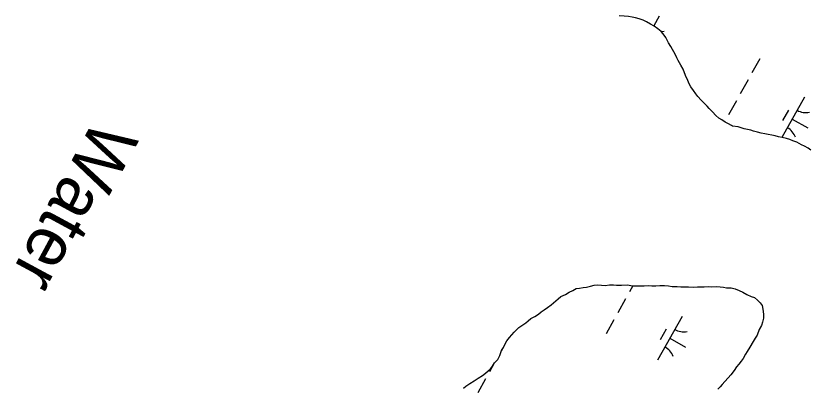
# Model space of a CAD drawing. Extents: x 3923531 to 3943530, y 207391 to 229799.
# Drawn here: x 3927358 to 3928152, y 213557 to 213929 of the extents above; entities that cross this region are included whole.
import ezdxf

# ---------------------------------------------------------------- set-up
doc = ezdxf.new("R2010")
doc.units = 0
doc.layers.add('V-RIVR-IDEN', color=7, linetype='Continuous')
doc.layers.add('V-WETL-SWMP', color=7, linetype='Continuous')

msp = doc.modelspace()

# ---------------------------------------------------------------- linework, layer by layer
at = {"layer": 'V-WETL-SWMP'}
for p, q in [((3927966.19, 213928.5), (3927961.2, 213928.91)), ((3927970.49, 213928.44), (3927966.19, 213928.5)), ((3927974.27, 213927.53), (3927970.49, 213928.44)), ((3927977.71, 213926.97), (3927974.27, 213927.53)), ((3927981.31, 213926.06), (3927977.71, 213926.97)), ((3927985.25, 213924.63), (3927981.31, 213926.06)), ((3928001.33, 213928.76), (3927995.87, 213918.99)), ((3927988.68, 213923.03), (3927985.25, 213924.63)), ((3927992.78, 213920.74), (3927988.68, 213923.03)), ((3927996.2, 213918.8), (3927992.78, 213920.74)), ((3927999.95, 213916), (3927996.2, 213918.8)), ((3928003.19, 213913.2), (3927999.95, 213916)), ((3928005.4, 213910.93), (3928003.19, 213913.2)), ((3928007.93, 213907.28), (3928005.4, 213910.93)), ((3928010.79, 213902.07), (3928007.93, 213907.28)), ((3928012.98, 213898.26), (3928010.79, 213902.07)), ((3928014.66, 213895.31), (3928012.98, 213898.26)), ((3928017.19, 213890.8), (3928014.66, 213895.31)), ((3928019.03, 213887.15), (3928017.19, 213890.8)), ((3928020.37, 213884.21), (3928019.03, 213887.15)), ((3928101.87, 213886), (3928094.06, 213872.04)), ((3928022.89, 213879.52), (3928020.37, 213884.21)), ((3928025.25, 213875.53), (3928022.89, 213879.52)), ((3928027.58, 213869.3), (3928025.25, 213875.53)), ((3928029.93, 213864.45), (3928027.58, 213869.3)), ((3928031.43, 213860.98), (3928029.93, 213864.45)), ((3928090.16, 213865.05), (3928082.36, 213851.08)), ((3928033.11, 213857.86), (3928031.43, 213860.98)), ((3928035.65, 213854.21), (3928033.11, 213857.86)), ((3928038.01, 213850.91), (3928035.65, 213854.21)), ((3928040.05, 213848.3), (3928038.01, 213850.91)), ((3928043.27, 213844.64), (3928040.05, 213848.3)), ((3928146.54, 213847.64), (3928124.02, 213807.32)), ((3928046.16, 213841.67), (3928043.27, 213844.64)), ((3928049.22, 213838.53), (3928046.16, 213841.67)), ((3928051.43, 213836.26), (3928049.22, 213838.53)), ((3928078.46, 213844.1), (3928070.65, 213830.13)), ((3928054.65, 213832.95), (3928051.43, 213836.26)), ((3928057.88, 213829.46), (3928054.65, 213832.95)), ((3928061.12, 213826.66), (3928057.88, 213829.46)), ((3928130.54, 213834.81), (3928124.69, 213824.34)), ((3928063.85, 213824.9), (3928061.12, 213826.66)), ((3928067.44, 213822.79), (3928063.85, 213824.9)), ((3928070.69, 213821.02), (3928067.44, 213822.79)), ((3928134.35, 213825.81), (3928150.07, 213817.03)), ((3928073.77, 213819.43), (3928070.69, 213821.02)), ((3928074.79, 213818.56), (3928073.77, 213819.43)), ((3928080.29, 213818.14), (3928074.79, 213818.56)), ((3928083.2, 213816.9), (3928080.29, 213818.14)), ((3928086.29, 213816), (3928083.2, 213816.9)), ((3928089.55, 213815.26), (3928086.29, 213816)), ((3928092.82, 213814.53), (3928089.55, 213815.26)), ((3928095.73, 213813.63), (3928092.82, 213814.53)), ((3928099.68, 213812.72), (3928095.73, 213813.63)), ((3928103.29, 213811.81), (3928099.68, 213812.72)), ((3928107.07, 213811.07), (3928103.29, 213811.81)), ((3928110.33, 213810.34), (3928107.07, 213811.07)), ((3928114.11, 213809.6), (3928110.33, 213810.34)), ((3928117.37, 213809.04), (3928114.11, 213809.6)), ((3928120.63, 213808.14), (3928117.37, 213809.04)), ((3928124.41, 213807.22), (3928120.63, 213808.14)), ((3928128.53, 213806.48), (3928124.41, 213807.22)), ((3928131.79, 213805.4), (3928128.53, 213806.48)), ((3928135.05, 213804.16), (3928131.79, 213805.4)), ((3928138.82, 213802.56), (3928135.05, 213804.16)), ((3928143.61, 213800.08), (3928138.82, 213802.56)), ((3928146.51, 213798.66), (3928143.61, 213800.08)), ((3928150.28, 213796.55), (3928146.51, 213798.66)), ((3928152.84, 213794.79), (3928150.28, 213796.55)), ((3927915.02, 213654.39), (3927918.18, 213656.32)), ((3927918.18, 213656.32), (3927921.72, 213656.66)), ((3927921.72, 213656.66), (3927925.27, 213657.4)), ((3927925.27, 213657.4), (3927928.81, 213657.74)), ((3927928.81, 213657.74), (3927932.75, 213658.87)), ((3927932.75, 213658.87), (3927936.29, 213659.61)), ((3927936.29, 213659.61), (3927939.44, 213659.96)), ((3927939.44, 213659.96), (3927943.76, 213659.9)), ((3927943.76, 213659.9), (3927947.29, 213659.46)), ((3927947.29, 213659.46), (3927951.62, 213660.19)), ((3927951.62, 213660.19), (3927955.54, 213660.14)), ((3927955.54, 213660.14), (3927958.68, 213659.71)), ((3927958.68, 213659.71), (3927963.79, 213659.64)), ((3927963.79, 213659.64), (3927969.68, 213659.95)), ((3927969.68, 213659.95), (3927974.77, 213659.1)), ((3927975.1, 213659.1), (3927971.67, 213652.95)), ((3927974.77, 213659.1), (3927979.09, 213659.04)), ((3927979.09, 213659.04), (3927983.02, 213658.99)), ((3927983.02, 213658.99), (3927986.16, 213658.95)), ((3927986.16, 213658.95), (3927990.88, 213659.28)), ((3927990.88, 213659.28), (3927994.02, 213659.24)), ((3927994.02, 213659.24), (3927997.95, 213659.19)), ((3927997.95, 213659.19), (3928001.88, 213659.53)), ((3928001.88, 213659.53), (3928006.59, 213659.46)), ((3928006.59, 213659.46), (3928010.51, 213659.02)), ((3928010.51, 213659.02), (3928014.43, 213658.58)), ((3928014.43, 213658.58), (3928019.15, 213658.51)), ((3928019.15, 213658.51), (3928023.07, 213658.07)), ((3928023.07, 213658.07), (3928026.6, 213658.02)), ((3928026.6, 213658.02), (3928030.53, 213657.97)), ((3928030.53, 213657.97), (3928035.24, 213657.91)), ((3928035.24, 213657.91), (3928039.56, 213658.24)), ((3928039.56, 213658.24), (3928042.71, 213658.2)), ((3928042.71, 213658.2), (3928046.24, 213658.15)), ((3928046.24, 213658.15), (3928050.56, 213658.49)), ((3928050.56, 213658.49), (3928053.7, 213658.06)), ((3928053.7, 213658.06), (3928058.81, 213658.38)), ((3928058.81, 213658.38), (3928062.34, 213657.94)), ((3928062.34, 213657.94), (3928065.48, 213657.9)), ((3928065.48, 213657.9), (3928068.61, 213657.07)), ((3928068.61, 213657.07), (3928073.32, 213657.01)), ((3928073.32, 213657.01), (3928077.24, 213656.17)), ((3928077.24, 213656.17), (3928081.15, 213654.55)), ((3927900.37, 213645.95), (3927903.15, 213648.27)), ((3927903.15, 213648.27), (3927907.5, 213650.57)), ((3927907.5, 213650.57), (3927911.46, 213652.87)), ((3927911.46, 213652.87), (3927915.02, 213654.39)), ((3928081.15, 213654.55), (3928085.05, 213652.93)), ((3928085.05, 213652.93), (3928088.95, 213650.52)), ((3928088.95, 213650.52), (3928093.24, 213648.5)), ((3928093.24, 213648.5), (3928096.76, 213647.28)), ((3928096.76, 213647.28), (3928099.48, 213644.88)), ((3927889.66, 213637.45), (3927893.23, 213640.15)), ((3927893.23, 213640.15), (3927897.99, 213644.01)), ((3927897.99, 213644.01), (3927900.37, 213645.95)), ((3927967.77, 213645.97), (3927959.97, 213632)), ((3928099.48, 213644.88), (3928102.19, 213642.1)), ((3928102.19, 213642.1), (3928104.12, 213639.32)), ((3928104.12, 213639.32), (3928104.85, 213635.78)), ((3927880.54, 213630.89), (3927883.32, 213633.21)), ((3927883.32, 213633.21), (3927886.48, 213635.13)), ((3927886.48, 213635.13), (3927889.66, 213637.45)), ((3928104.85, 213635.78), (3928105.57, 213630.66)), ((3927867.85, 213622.03), (3927870.23, 213623.96)), ((3927870.23, 213623.96), (3927873.01, 213626.28)), ((3927873.01, 213626.28), (3927876.97, 213628.58)), ((3927876.97, 213628.58), (3927880.54, 213630.89)), ((3927956.06, 213625.02), (3927948.26, 213611.05)), ((3928024.15, 213628.55), (3927999.77, 213584.9)), ((3928105.52, 213626.74), (3928104.68, 213622.82)), ((3928105.57, 213630.66), (3928105.52, 213626.74)), ((3927856.34, 213612.75), (3927858.73, 213615.08)), ((3927858.73, 213615.08), (3927861.12, 213617.4)), ((3927861.12, 213617.4), (3927863.89, 213619.33)), ((3927863.89, 213619.33), (3927867.85, 213622.03)), ((3928008.15, 213615.73), (3928002.3, 213605.25)), ((3928101.44, 213615.4), (3928099.41, 213609.93)), ((3928103.46, 213619.3), (3928101.44, 213615.4)), ((3928104.68, 213622.82), (3928103.46, 213619.3)), ((3927849.16, 213604.21), (3927851.56, 213607.32)), ((3927851.56, 213607.32), (3927853.95, 213610.04)), ((3927853.95, 213610.04), (3927856.34, 213612.75)), ((3928099.41, 213609.93), (3928097.4, 213606.82)), ((3927845.54, 213597.58), (3927847.14, 213600.31)), ((3927847.14, 213600.31), (3927849.16, 213604.21)), ((3928011.96, 213606.73), (3928027.67, 213597.95)), ((3928095.39, 213603.31), (3928091.79, 213597.86)), ((3928097.4, 213606.82), (3928095.39, 213603.31)), ((3927841.89, 213589.38), (3927843.53, 213594.46)), ((3927844.32, 213595.7), (3927843.39, 213594.03)), ((3927843.53, 213594.46), (3927845.54, 213597.58)), ((3928089.37, 213593.57), (3928087.77, 213590.84)), ((3928091.79, 213597.86), (3928089.37, 213593.57)), ((3927836.69, 213581.99), (3927839.88, 213585.48)), ((3927839.88, 213585.48), (3927841.89, 213589.38)), ((3928083.35, 213583.83), (3928080.96, 213580.72)), ((3928085.35, 213586.55), (3928083.35, 213583.83)), ((3928087.77, 213590.84), (3928085.35, 213586.55)), ((3927830.3, 213574.22), (3927832.68, 213576.15)), ((3927836.51, 213581.71), (3927831.69, 213573.08)), ((3927832.68, 213576.15), (3927834.68, 213578.87)), ((3927834.68, 213578.87), (3927836.69, 213581.99)), ((3928078.56, 213578), (3928076.16, 213574.5)), ((3928080.96, 213580.72), (3928078.56, 213578)), ((3927820.39, 213566.89), (3927824.74, 213569.58)), ((3927824.74, 213569.58), (3927827.52, 213571.9)), ((3927827.52, 213571.9), (3927830.3, 213574.22)), ((3928072.96, 213570.22), (3928070.17, 213567.12)), ((3928076.16, 213574.5), (3928072.96, 213570.22)), ((3927808.1, 213558.8), (3927812.07, 213561.5)), ((3927812.07, 213561.5), (3927816.42, 213564.19)), ((3927816.42, 213564.19), (3927820.39, 213566.89)), ((3927827.79, 213566.09), (3927819.98, 213552.13)), ((3928064.19, 213560.52), (3928062.2, 213558.19)), ((3928066.98, 213563.62), (3928064.19, 213560.52)), ((3928070.17, 213567.12), (3928066.98, 213563.62)), ((3927805.72, 213556.87), (3927808.1, 213558.8)), ((3928062.2, 213558.19), (3928059.81, 213555.86))]:
    msp.add_line(p, q, dxfattribs=at)
for centre, start, end in [((3928002.82, 213930.93), 270.77039, 281.58174), ((3928148.03, 213849.81), 240.03808, 281.58174), ((3928121.09, 213801.58), 20.03808, 61.58174), ((3928025.64, 213630.73), 240.03808, 281.58174), ((3927998.7, 213582.5), 20.03808, 61.58174)]:
    msp.add_arc(centre, 17.62, start, end, dxfattribs=at)

# ---------------------------------------------------------------- texts
at = {"layer": 'V-RIVR-IDEN'}
msp.add_text('Water', height=50, rotation=241.58945, dxfattribs=at).set_placement((3927437.43, 213828.11))

doc.saveas('drawing.dxf')
